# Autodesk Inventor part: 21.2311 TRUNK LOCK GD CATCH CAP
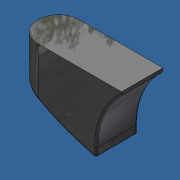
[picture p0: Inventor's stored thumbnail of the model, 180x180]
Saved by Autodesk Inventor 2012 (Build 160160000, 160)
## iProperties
Created: 2014-09
Part Number: 21.2311 TRUNK LOCK GD CATCH CAP
Material: ABS Plastic
Document SubType Name: Modeling
Designer: Admin
Density: 1.06 g/cm^3
Mass: 4.86881 g
Surface Area: 17.2547 cm^2
Volume: 4.59321 cm^3
Author: Admin
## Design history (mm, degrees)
feature "Base1"
body "Solid1"
